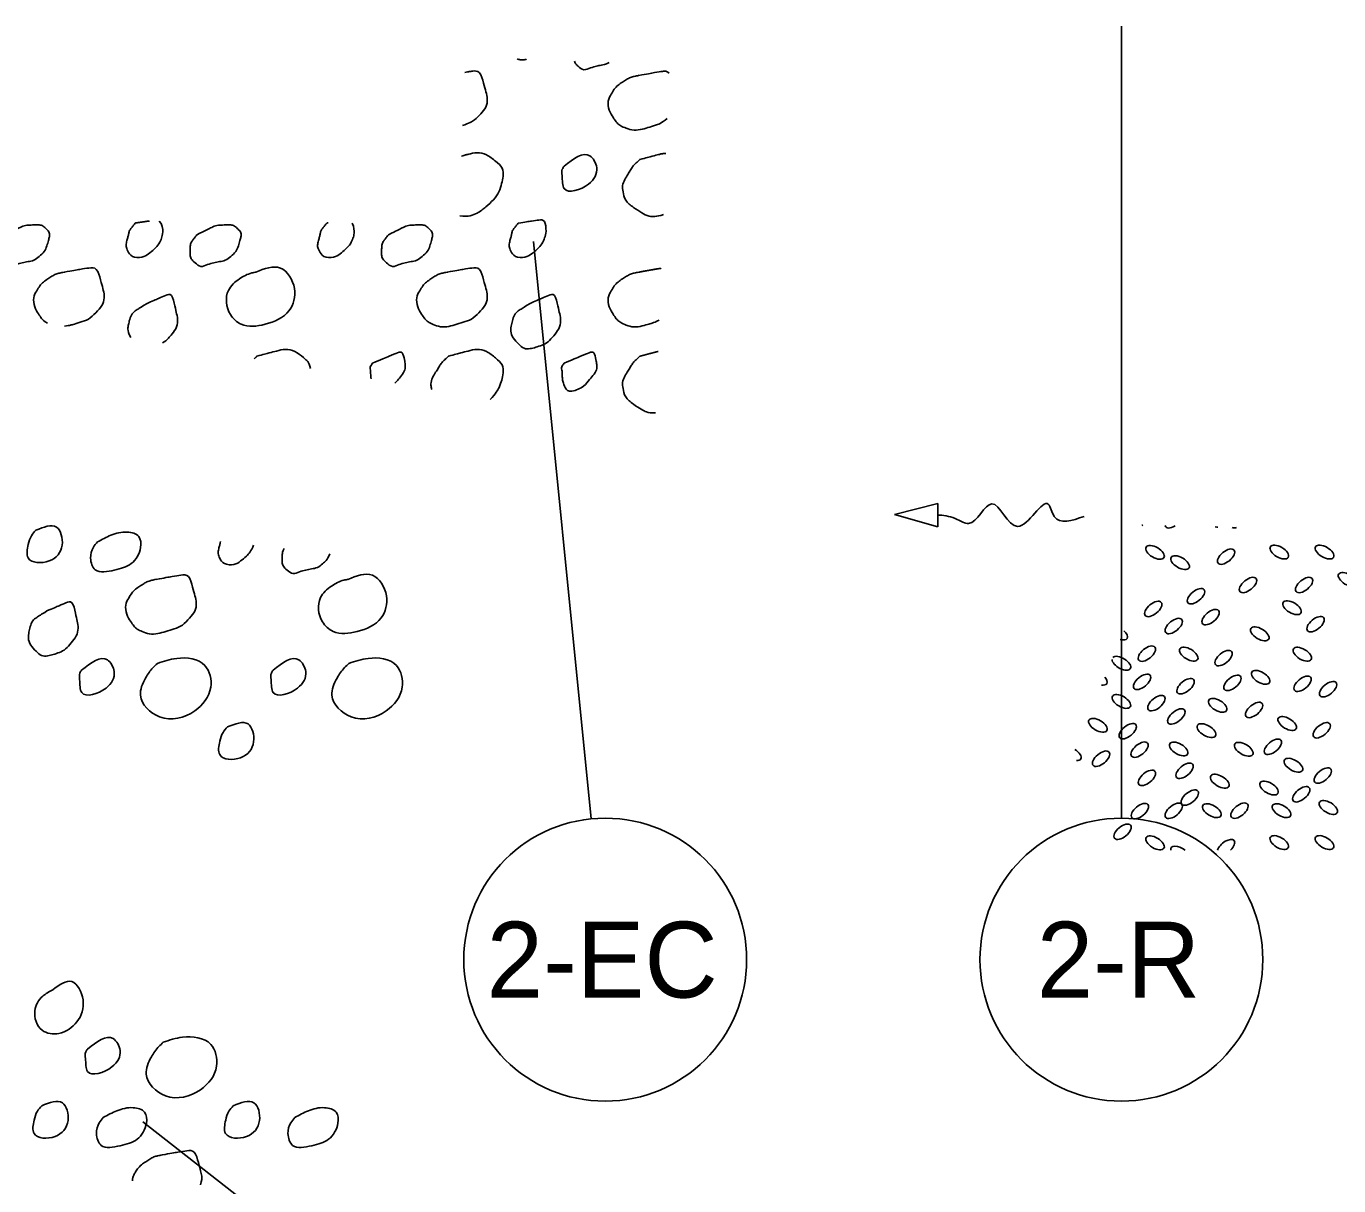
# Model space of a CAD drawing. Extents: x 1785 to 2465, y -264 to 295.
# Drawn here: x 2190.33 to 2238.79, y -12.46 to 30.33 of the extents above; entities that cross this region are included whole.
import ezdxf

# ---------------------------------------------------------------- set-up
doc = ezdxf.new("R2010")
doc.units = 0
for name, color, linetype in [('DR_P_Culvert', 7, 'Continuous'), ('DR_X_Erosion_Control', 7, 'Continuous'), ('PV_P_EOP', 7, 'Continuous'), ('PV_P_Shoulder', 7, 'Continuous'), ('TX_P_1', 7, 'Continuous')]:
    doc.layers.add(name, color=color, linetype=linetype)

msp = doc.modelspace()

# ---------------------------------------------------------------- linework, layer by layer
at = {"layer": 'DR_P_Culvert'}
for p, q in [((2230.769, 30.332), (2230.769, 1.105)), ((2211.19, 1.079), (2209.066, 22.389))]:
    msp.add_line(p, q, dxfattribs=at)
at = {"layer": 'DR_X_Erosion_Control'}
for centre, major_axis, start_param, end_param in [((2231.451, 12.088), (0.296, 0.243), 4.552972, 4.667645), ((2232.702, 12.099), (0.296, 0.243), 2.867084, 4.464389), ((2234.109, 12.103), (0.33, -0.195), 5.371409, 5.718624), ((2235.129, 12.103), (0.296, 0.243), 3.343649, 3.987824), ((2230.655, 7.936), (0.33, -0.195), 0, 1.210677), ((2230.655, 7.936), (0.33, -0.195), 5.214671, 6.283185), ((2230.768, 6.822), (0.33, -0.195), 3.418651, 6.283185), ((2230.768, 6.822), (0.33, -0.195), 0, 3.006696), ((2229.901, 6.268), (0.33, -0.195), 0, 1.037843), ((2229.901, 6.268), (0.33, -0.195), 5.387504, 6.283185), ((2228.935, 3.484), (0.33, -0.195), 0, 1.532687), ((2228.935, 3.484), (0.33, -0.195), 5.535335, 6.283185), ((2232.935, -0.186), (0.33, -0.195), 1.299888, 3.572242), ((2234.632, 0.034), (0.296, 0.243), 0, 2.52413), ((2234.632, 0.034), (0.296, 0.243), 4.857893, 6.283185)]:
    msp.add_ellipse(centre, major_axis=major_axis, ratio=0.503326, start_param=start_param, end_param=end_param, dxfattribs=at)
for centre, major_axis in [((2232.011, 10.915), (0.33, -0.195)), ((2236.598, 10.926), (0.33, -0.195)), ((2238.27, 10.926), (0.33, -0.195)), ((2232.935, 10.536), (0.33, -0.195)), ((2234.632, 10.756), (0.296, 0.243)), ((2239.121, 9.913), (0.33, -0.195)), ((2235.443, 9.71), (0.296, 0.243)), ((2237.516, 9.71), (0.296, 0.243)), ((2233.523, 9.295), (0.296, 0.243)), ((2231.944, 8.826), (0.296, 0.243)), ((2234.061, 8.524), (0.296, 0.243)), ((2237.069, 8.871), (0.33, -0.195)), ((2232.703, 8.196), (0.296, 0.243)), ((2237.937, 8.264), (0.296, 0.243)), ((2235.877, 7.907), (0.33, -0.195)), ((2231.708, 7.177), (0.296, 0.243)), ((2233.254, 7.158), (0.33, -0.195)), ((2234.541, 7.013), (0.296, 0.243)), ((2237.449, 7.156), (0.33, -0.195)), ((2231.531, 6.136), (0.296, 0.243)), ((2234.87, 6.097), (0.296, 0.243)), ((2235.91, 6.302), (0.33, -0.195)), ((2237.457, 6.066), (0.296, 0.243)), ((2233.136, 5.975), (0.296, 0.243)), ((2238.4, 5.863), (0.296, 0.243)), ((2230.768, 5.413), (0.33, -0.195)), ((2232.062, 5.351), (0.296, 0.243)), ((2234.323, 5.269), (0.33, -0.195)), ((2235.667, 5.098), (0.296, 0.243)), ((2232.797, 4.858), (0.296, 0.243)), ((2236.893, 4.598), (0.33, -0.195)), ((2229.901, 4.532), (0.33, -0.195)), ((2231.001, 4.315), (0.296, 0.243)), ((2233.911, 4.336), (0.33, -0.195)), ((2238.166, 4.348), (0.296, 0.243)), ((2231.441, 3.633), (0.296, 0.243)), ((2232.883, 3.659), (0.33, -0.195)), ((2235.287, 3.648), (0.33, -0.195)), ((2236.363, 3.74), (0.296, 0.243)), ((2230.018, 3.299), (0.296, 0.243)), ((2231.711, 2.59), (0.296, 0.243)), ((2233.101, 2.853), (0.296, 0.243)), ((2237.122, 3.058), (0.33, -0.195)), ((2238.205, 2.676), (0.296, 0.243)), ((2234.403, 2.468), (0.33, -0.195)), ((2236.219, 2.216), (0.33, -0.195)), ((2233.295, 1.863), (0.296, 0.243)), ((2237.409, 1.986), (0.296, 0.243)), ((2231.451, 1.366), (0.296, 0.243)), ((2232.702, 1.377), (0.296, 0.243)), ((2234.109, 1.381), (0.33, -0.195)), ((2235.129, 1.381), (0.296, 0.243)), ((2236.682, 1.381), (0.33, -0.195)), ((2238.41, 1.499), (0.33, -0.195)), ((2230.81, 0.604), (0.296, 0.243)), ((2236.598, 0.204), (0.33, -0.195)), ((2238.27, 0.204), (0.33, -0.195)), ((2232.011, 0.193), (0.33, -0.195))]:
    msp.add_ellipse(centre, major_axis=major_axis, ratio=0.503326, dxfattribs=at)
at = {"layer": 'PV_P_EOP'}
for p, q in [((2222.39, 12.307), (2223.994, 12.72)), ((2223.994, 12.72), (2223.986, 11.862)), ((2223.986, 11.862), (2222.39, 12.307))]:
    msp.add_line(p, q, dxfattribs=at)
msp.add_spline([(2223.988, 12.287), (2224.051, 12.286), (2224.708, 12.13), (2225.123, 11.981), (2225.979, 12.708), (2226.941, 11.873), (2228.069, 12.688), (2228.291, 12.239), (2229.389, 12.24)], degree=3, dxfattribs=at)
at = {"layer": 'PV_P_Shoulder'}
for points, degree in [([(2208.794, 29.112), (2208.685, 29.088), (2208.564, 29.092), (2208.458, 29.125)], 2), ([(2206.519, 28.63), (2206.608, 28.645), (2206.696, 28.659), (2206.784, 28.671), (2207.087, 28.713), (2207.227, 28.194), (2207.303, 27.911), (2207.372, 27.653), (2207.327, 27.338), (2207.109, 27.098), (2206.905, 26.872), (2206.684, 26.753), (2206.444, 26.666)], 3), ([(2211.857, 28.992), (2211.707, 28.92), (2211.553, 28.897), (2211.398, 28.861), (2211.172, 28.808), (2210.915, 28.675), (2210.694, 28.873), (2210.635, 28.926), (2210.594, 28.983), (2210.568, 29.043)], 3), ([(2212.948, 28.519), (2213.25, 28.571), (2213.553, 28.629), (2213.856, 28.671), (2213.937, 28.682), (2214.007, 28.653), (2214.067, 28.598)], 3), ([(2214, 26.927), (2213.782, 26.753), (2213.546, 26.668), (2213.289, 26.593), (2213.007, 26.509), (2212.69, 26.479), (2212.409, 26.598), (2212.239, 26.669), (2212.115, 26.794), (2212.011, 26.954), (2211.838, 27.222), (2211.787, 27.591), (2211.938, 27.844), (2212.038, 28.012), (2212.174, 28.16), (2212.348, 28.271), (2212.495, 28.365), (2212.636, 28.453), (2212.799, 28.488), (2212.854, 28.499), (2212.909, 28.511), (2212.964, 28.523)], 3), ([(2206.402, 25.543), (2206.478, 25.563), (2206.553, 25.583), (2206.629, 25.603), (2206.976, 25.692), (2207.324, 25.629), (2207.671, 25.339), (2207.94, 25.115), (2207.957, 24.782), (2207.886, 24.534), (2207.796, 24.221), (2207.598, 23.924), (2207.294, 23.664), (2207.017, 23.427), (2206.66, 23.295), (2206.336, 23.331)], 3), ([(2213.859, 23.38), (2213.587, 23.295), (2213.303, 23.304), (2213.069, 23.443), (2212.754, 23.629), (2212.422, 23.909), (2212.361, 24.239), (2212.323, 24.445), (2212.43, 24.684), (2212.551, 24.876), (2212.637, 25.013), (2212.714, 25.151), (2212.828, 25.261), (2212.881, 25.313), (2212.935, 25.364), (2212.989, 25.416)], 3), ([(2212.989, 25.416), (2213.226, 25.479), (2213.464, 25.541), (2213.701, 25.603), (2213.784, 25.624), (2213.866, 25.637), (2213.949, 25.64)], 3), ([(2189.559, 22.637), (2189.726, 22.72), (2189.892, 22.803), (2190.059, 22.887), (2190.242, 22.978), (2190.462, 22.996), (2190.661, 23.002), (2190.808, 23.006), (2190.95, 22.971), (2191.083, 22.84), (2191.204, 22.72), (2191.187, 22.56), (2191.151, 22.433), (2191.092, 22.223), (2191.014, 22.01), (2190.809, 21.84), (2190.609, 21.674), (2190.398, 21.65), (2190.183, 21.6), (2189.957, 21.547), (2189.7, 21.414), (2189.479, 21.612), (2189.334, 21.742), (2189.304, 21.894), (2189.308, 22.043), (2189.311, 22.176), (2189.328, 22.332), (2189.411, 22.443), (2189.46, 22.509), (2189.51, 22.572), (2189.559, 22.637)], 3), ([(2195.235, 23.144), (2195.363, 23.027), (2195.385, 22.682), (2195.328, 22.525), (2195.249, 22.308), (2195.051, 22.092), (2194.848, 21.937), (2194.638, 21.776), (2194.196, 21.803), (2194.074, 22.05), (2193.998, 22.205), (2194.036, 22.386), (2194.079, 22.542), (2194.11, 22.651), (2194.124, 22.777), (2194.196, 22.868), (2194.249, 22.936), (2194.303, 23.003), (2194.356, 23.07)], 3), ([(2194.356, 23.07), (2194.53, 23.095), (2194.705, 23.122), (2194.879, 23.147)], 2), ([(2196.631, 22.637), (2196.797, 22.72), (2196.964, 22.803), (2197.131, 22.887), (2197.314, 22.978), (2197.533, 22.996), (2197.733, 23.002), (2197.88, 23.006), (2198.022, 22.971), (2198.154, 22.84), (2198.276, 22.72), (2198.258, 22.56), (2198.223, 22.433), (2198.164, 22.223), (2198.085, 22.01), (2197.881, 21.84), (2197.681, 21.674), (2197.469, 21.65), (2197.254, 21.6), (2197.029, 21.547), (2196.771, 21.414), (2196.551, 21.612), (2196.406, 21.742), (2196.375, 21.894), (2196.379, 22.043), (2196.383, 22.176), (2196.399, 22.332), (2196.483, 22.443), (2196.532, 22.509), (2196.581, 22.572), (2196.631, 22.637)], 3), ([(2202.362, 23.068), (2202.44, 22.917), (2202.447, 22.656), (2202.399, 22.525), (2202.32, 22.308), (2202.123, 22.092), (2201.919, 21.937), (2201.71, 21.776), (2201.268, 21.803), (2201.146, 22.05), (2201.07, 22.205), (2201.108, 22.386), (2201.151, 22.542), (2201.182, 22.651), (2201.196, 22.777), (2201.268, 22.868), (2201.321, 22.936), (2201.374, 23.003), (2201.428, 23.07)], 3), ([(2201.428, 23.07), (2201.445, 23.072), (2201.462, 23.075), (2201.479, 23.077)], 2), ([(2203.703, 22.637), (2203.869, 22.72), (2204.036, 22.803), (2204.203, 22.887), (2204.386, 22.978), (2204.605, 22.996), (2204.804, 23.002), (2204.951, 23.006), (2205.093, 22.971), (2205.226, 22.84), (2205.347, 22.72), (2205.33, 22.56), (2205.294, 22.433), (2205.235, 22.223), (2205.157, 22.01), (2204.953, 21.84), (2204.753, 21.674), (2204.541, 21.65), (2204.326, 21.6), (2204.101, 21.547), (2203.843, 21.414), (2203.623, 21.612), (2203.477, 21.742), (2203.447, 21.894), (2203.451, 22.043), (2203.455, 22.176), (2203.471, 22.332), (2203.554, 22.443), (2203.604, 22.509), (2203.653, 22.572), (2203.703, 22.637)], 3), ([(2208.499, 23.07), (2208.754, 23.107), (2209.008, 23.147), (2209.263, 23.182), (2209.49, 23.212), (2209.543, 22.721), (2209.471, 22.525), (2209.392, 22.308), (2209.195, 22.092), (2208.991, 21.937), (2208.781, 21.776), (2208.339, 21.803), (2208.218, 22.05), (2208.141, 22.205), (2208.179, 22.386), (2208.223, 22.542), (2208.253, 22.651), (2208.268, 22.777), (2208.339, 22.868), (2208.393, 22.936), (2208.446, 23.003), (2208.499, 23.07)], 3), ([(2191.733, 21.258), (2192.035, 21.31), (2192.338, 21.368), (2192.641, 21.41), (2192.943, 21.452), (2193.084, 20.934), (2193.159, 20.65), (2193.228, 20.392), (2193.184, 20.077), (2192.966, 19.837), (2192.699, 19.542), (2192.403, 19.428), (2192.074, 19.332), (2191.968, 19.3), (2191.857, 19.277), (2191.745, 19.265)], 3), ([(2205.876, 21.258), (2206.179, 21.31), (2206.482, 21.368), (2206.784, 21.41), (2207.087, 21.452), (2207.227, 20.934), (2207.303, 20.65), (2207.372, 20.392), (2207.327, 20.077), (2207.109, 19.837), (2206.843, 19.542), (2206.547, 19.428), (2206.218, 19.332), (2205.935, 19.248), (2205.619, 19.218), (2205.338, 19.337), (2205.167, 19.409), (2205.043, 19.533), (2204.939, 19.693), (2204.766, 19.961), (2204.715, 20.33), (2204.866, 20.583), (2204.966, 20.751), (2205.102, 20.899), (2205.276, 21.01), (2205.423, 21.104), (2205.564, 21.192), (2205.728, 21.227), (2205.783, 21.238), (2205.838, 21.25), (2205.893, 21.262)], 3), ([(2212.948, 21.258), (2213.225, 21.306), (2213.503, 21.358), (2213.78, 21.399)], 2), ([(2191.119, 19.373), (2190.986, 19.448), (2190.884, 19.557), (2190.796, 19.693), (2190.623, 19.961), (2190.572, 20.33), (2190.723, 20.583), (2190.823, 20.751), (2190.959, 20.899), (2191.133, 21.01), (2191.28, 21.104), (2191.421, 21.192), (2191.584, 21.227), (2191.639, 21.238), (2191.694, 21.25), (2191.749, 21.262)], 3), ([(2213.704, 19.482), (2213.572, 19.42), (2213.434, 19.374), (2213.289, 19.332), (2213.007, 19.248), (2212.69, 19.218), (2212.409, 19.337), (2212.239, 19.409), (2212.115, 19.533), (2212.011, 19.693), (2211.838, 19.961), (2211.787, 20.33), (2211.938, 20.583), (2212.038, 20.751), (2212.174, 20.899), (2212.348, 21.01), (2212.495, 21.104), (2212.636, 21.192), (2212.799, 21.227), (2212.854, 21.238), (2212.909, 21.25), (2212.964, 21.262)], 3), ([(2194.764, 20.093), (2194.999, 20.194), (2195.233, 20.294), (2195.468, 20.395), (2195.711, 20.499), (2195.829, 19.966), (2195.883, 19.718), (2195.939, 19.456), (2195.871, 19.162), (2195.659, 18.908), (2195.564, 18.794), (2195.463, 18.709), (2195.357, 18.643)], 3), ([(2208.908, 20.093), (2209.142, 20.194), (2209.377, 20.294), (2209.611, 20.395), (2209.854, 20.499), (2209.973, 19.966), (2210.026, 19.718), (2210.083, 19.456), (2210.015, 19.162), (2209.803, 18.908), (2209.603, 18.669), (2209.376, 18.556), (2209.136, 18.483), (2208.944, 18.425), (2208.702, 18.416), (2208.514, 18.602), (2208.287, 18.826), (2208.202, 19.091), (2208.248, 19.32), (2208.284, 19.502), (2208.369, 19.742), (2208.539, 19.855), (2208.662, 19.936), (2208.785, 20.013), (2208.908, 20.093)], 3), ([(2194.187, 18.844), (2194.101, 19.004), (2194.074, 19.17), (2194.104, 19.32), (2194.141, 19.502), (2194.226, 19.742), (2194.396, 19.855), (2194.519, 19.936), (2194.642, 20.013), (2194.764, 20.093)], 3), ([(2198.745, 18.058), (2198.779, 18.091), (2198.812, 18.123), (2198.846, 18.155)], 2), ([(2198.846, 18.155), (2199.083, 18.218), (2199.32, 18.28), (2199.558, 18.342), (2199.904, 18.431), (2200.253, 18.368), (2200.599, 18.078), (2200.729, 17.97), (2200.8, 17.836), (2200.831, 17.699)], 3), ([(2203.119, 17.903), (2203.436, 18.031), (2203.753, 18.168), (2204.069, 18.288), (2204.225, 18.348), (2204.307, 18), (2204.321, 17.852), (2204.34, 17.652), (2204.187, 17.444), (2204.023, 17.247), (2203.999, 17.218), (2203.971, 17.189), (2203.94, 17.163)], 3), ([(2205.301, 16.928), (2205.296, 16.945), (2205.292, 16.961), (2205.289, 16.978), (2205.251, 17.184), (2205.358, 17.423), (2205.479, 17.615), (2205.566, 17.752), (2205.642, 17.89), (2205.756, 18), (2205.81, 18.052), (2205.864, 18.103), (2205.918, 18.155)], 3), ([(2205.918, 18.155), (2206.155, 18.218), (2206.392, 18.28), (2206.629, 18.342), (2206.976, 18.431), (2207.324, 18.368), (2207.671, 18.078), (2207.94, 17.854), (2207.957, 17.521), (2207.886, 17.273), (2207.813, 17.02), (2207.67, 16.777), (2207.457, 16.556)], 3), ([(2210.191, 17.903), (2210.508, 18.031), (2210.824, 18.168), (2211.141, 18.288), (2211.297, 18.348), (2211.379, 18), (2211.393, 17.852), (2211.411, 17.652), (2211.259, 17.444), (2211.094, 17.247), (2210.871, 16.978), (2210.31, 16.783), (2210.194, 17.078), (2210.133, 17.235), (2210.123, 17.396), (2210.116, 17.558), (2210.113, 17.639), (2210.083, 17.728), (2210.124, 17.8), (2210.146, 17.836), (2210.169, 17.869), (2210.191, 17.903)], 3), ([(2213.568, 16.066), (2213.392, 16.057), (2213.22, 16.092), (2213.069, 16.182), (2212.754, 16.368), (2212.422, 16.648), (2212.361, 16.978), (2212.323, 17.184), (2212.43, 17.423), (2212.551, 17.615), (2212.637, 17.752), (2212.714, 17.89), (2212.828, 18), (2212.881, 18.052), (2212.935, 18.103), (2212.989, 18.155)], 3), ([(2212.989, 18.155), (2213.212, 18.214), (2213.435, 18.273), (2213.658, 18.33)], 2), ([(2203.063, 17.314), (2203.052, 17.395), (2203.048, 17.476), (2203.044, 17.558), (2203.041, 17.639), (2203.011, 17.728), (2203.053, 17.8), (2203.074, 17.836), (2203.098, 17.869), (2203.119, 17.903)], 3), ([(2198.724, 11.18), (2198.644, 10.966), (2198.448, 10.752), (2198.246, 10.598), (2198.037, 10.437), (2197.595, 10.464), (2197.473, 10.711), (2197.396, 10.867), (2197.435, 11.047), (2197.478, 11.203), (2197.488, 11.24), (2197.497, 11.279), (2197.506, 11.318)], 3), ([(2201.542, 10.861), (2201.487, 10.731), (2201.408, 10.607), (2201.28, 10.501), (2201.08, 10.335), (2200.868, 10.311), (2200.653, 10.261), (2200.428, 10.209), (2200.17, 10.075), (2199.95, 10.273), (2199.804, 10.403), (2199.774, 10.555), (2199.778, 10.704), (2199.781, 10.817), (2199.793, 10.948), (2199.849, 11.053)], 3), ([(2195.131, 9.919), (2195.434, 9.971), (2195.737, 10.029), (2196.04, 10.071), (2196.342, 10.113), (2196.482, 9.595), (2196.558, 9.311), (2196.627, 9.053), (2196.582, 8.738), (2196.365, 8.498), (2196.098, 8.203), (2195.802, 8.089), (2195.473, 7.993), (2195.191, 7.91), (2194.874, 7.879), (2194.593, 7.998), (2194.422, 8.07), (2194.298, 8.194), (2194.195, 8.354), (2194.022, 8.622), (2193.97, 8.991), (2194.121, 9.244), (2194.221, 9.412), (2194.357, 9.56), (2194.531, 9.671), (2194.679, 9.765), (2194.82, 9.853), (2194.983, 9.888), (2195.038, 9.899), (2195.093, 9.911), (2195.148, 9.923)], 3), ([(2191.091, 8.754), (2191.326, 8.855), (2191.56, 8.955), (2191.795, 9.056), (2192.038, 9.16), (2192.156, 8.627), (2192.21, 8.379), (2192.266, 8.117), (2192.198, 7.823), (2191.986, 7.569), (2191.787, 7.33), (2191.559, 7.217), (2191.32, 7.144), (2191.128, 7.086), (2190.886, 7.077), (2190.698, 7.263), (2190.47, 7.488), (2190.386, 7.752), (2190.431, 7.981), (2190.468, 8.163), (2190.553, 8.403), (2190.723, 8.516), (2190.846, 8.597), (2190.969, 8.674), (2191.091, 8.754)], 3), ([(2195.347, -11.324), (2195.65, -11.273), (2195.953, -11.215), (2196.256, -11.173), (2196.558, -11.131), (2196.698, -11.649), (2196.774, -11.933), (2196.816, -12.089), (2196.816, -12.266), (2196.761, -12.434)], 3), ([(2194.251, -12.28), (2194.26, -12.179), (2194.288, -12.083), (2194.337, -11.999), (2194.437, -11.832), (2194.573, -11.684), (2194.747, -11.573), (2194.895, -11.479), (2195.036, -11.391), (2195.199, -11.356), (2195.254, -11.344), (2195.309, -11.333), (2195.364, -11.321)], 3)]:
    msp.add_open_spline(points, degree=degree, dxfattribs=at)
for points in [[(2210.191, 25.164), (2211.141, 25.549), (2211.393, 25.113), (2211.094, 24.508), (2210.194, 24.339), (2210.116, 24.819), (2210.124, 25.061), (2210.191, 25.164)], [(2198.804, 21.258), (2199.713, 21.41), (2200.231, 20.65), (2200.038, 19.837), (2199.146, 19.332), (2198.266, 19.337), (2197.868, 19.693), (2197.794, 20.583), (2198.204, 21.01), (2198.656, 21.227), (2198.821, 21.262)], [(2190.683, 11.731), (2191.446, 11.843), (2191.655, 11.186), (2191.175, 10.598), (2190.401, 10.711), (2190.406, 11.203), (2190.523, 11.529), (2190.683, 11.731)], [(2192.958, 11.298), (2193.458, 11.548), (2194.06, 11.663), (2194.481, 11.501), (2194.55, 11.094), (2194.208, 10.501), (2193.581, 10.261), (2192.878, 10.273), (2192.706, 10.704), (2192.81, 11.104), (2192.958, 11.298)], [(2202.203, 9.919), (2203.111, 10.071), (2203.63, 9.311), (2203.436, 8.498), (2202.545, 7.993), (2201.665, 7.998), (2201.266, 8.354), (2201.193, 9.244), (2201.603, 9.671), (2202.055, 9.888), (2202.22, 9.923)], [(2192.375, 6.564), (2193.325, 6.949), (2193.576, 6.513), (2193.278, 5.908), (2192.378, 5.739), (2192.3, 6.219), (2192.308, 6.461), (2192.375, 6.564)], [(2195.173, 6.816), (2195.885, 7.003), (2196.926, 6.739), (2197.141, 5.934), (2196.55, 5.064), (2195.253, 4.843), (2194.545, 5.639), (2194.735, 6.276), (2195.011, 6.661), (2195.173, 6.816)], [(2199.446, 6.564), (2200.396, 6.949), (2200.648, 6.513), (2200.35, 5.908), (2199.45, 5.739), (2199.371, 6.219), (2199.38, 6.461), (2199.446, 6.564)], [(2202.245, 6.816), (2202.956, 7.003), (2203.998, 6.739), (2204.213, 5.934), (2203.621, 5.064), (2202.325, 4.843), (2201.616, 5.639), (2201.806, 6.276), (2202.083, 6.661), (2202.245, 6.816)], [(2197.755, 4.47), (2198.518, 4.582), (2198.726, 3.925), (2198.246, 3.337), (2197.473, 3.45), (2197.478, 3.942), (2197.595, 4.268), (2197.755, 4.47)], [(2191.307, -5.228), (2192.011, -4.927), (2192.426, -5.603), (2192.202, -6.413), (2191.536, -6.838), (2190.914, -6.72), (2190.647, -6.002), (2190.939, -5.467), (2191.307, -5.228)], [(2192.591, -7.418), (2193.541, -7.033), (2193.792, -7.47), (2193.494, -8.075), (2192.594, -8.243), (2192.516, -7.763), (2192.524, -7.522), (2192.591, -7.418)], [(2195.389, -7.167), (2196.101, -6.98), (2197.142, -7.243), (2197.357, -8.048), (2196.766, -8.918), (2195.469, -9.14), (2194.761, -8.343), (2194.951, -7.707), (2195.227, -7.322), (2195.389, -7.167)], [(2190.899, -9.513), (2191.662, -9.401), (2191.871, -10.058), (2191.391, -10.646), (2190.617, -10.533), (2190.622, -10.041), (2190.739, -9.714), (2190.899, -9.513)], [(2193.174, -9.946), (2193.674, -9.696), (2194.276, -9.581), (2194.697, -9.743), (2194.766, -10.149), (2194.424, -10.743), (2193.797, -10.983), (2193.094, -10.971), (2192.922, -10.539), (2193.026, -10.139), (2193.174, -9.946)], [(2197.971, -9.513), (2198.734, -9.401), (2198.942, -10.058), (2198.462, -10.646), (2197.689, -10.533), (2197.694, -10.041), (2197.811, -9.714), (2197.971, -9.513)], [(2200.246, -9.946), (2200.746, -9.696), (2201.347, -9.581), (2201.769, -9.743), (2201.837, -10.149), (2201.496, -10.743), (2200.869, -10.983), (2200.166, -10.971), (2199.994, -10.539), (2200.097, -10.139), (2200.246, -9.946)]]:
    msp.add_spline(points, degree=3, dxfattribs=at)
at = {"layer": 'TX_P_1'}
msp.add_line((2220.737, -30.526), (2194.63, -10.098), dxfattribs=at)
for centre in [(2211.708, -4.117), (2230.769, -4.117)]:
    msp.add_circle(centre, 5.222, dxfattribs=at)

# ---------------------------------------------------------------- texts
for s, p in [('2-EC', (2207.329, -5.517)), ('2-R', (2227.645, -5.517))]:
    msp.add_text(s, height=2.8, dxfattribs=at).set_placement(p)

doc.saveas('drawing.dxf')
